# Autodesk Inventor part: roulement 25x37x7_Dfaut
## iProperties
Created: 2006-03
Part Number: roulement 25x37x7_Dfaut
Document SubType Name: Modeling
Designer: Flavien MARTY
Author: Flavien MARTY
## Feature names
1. Base1
